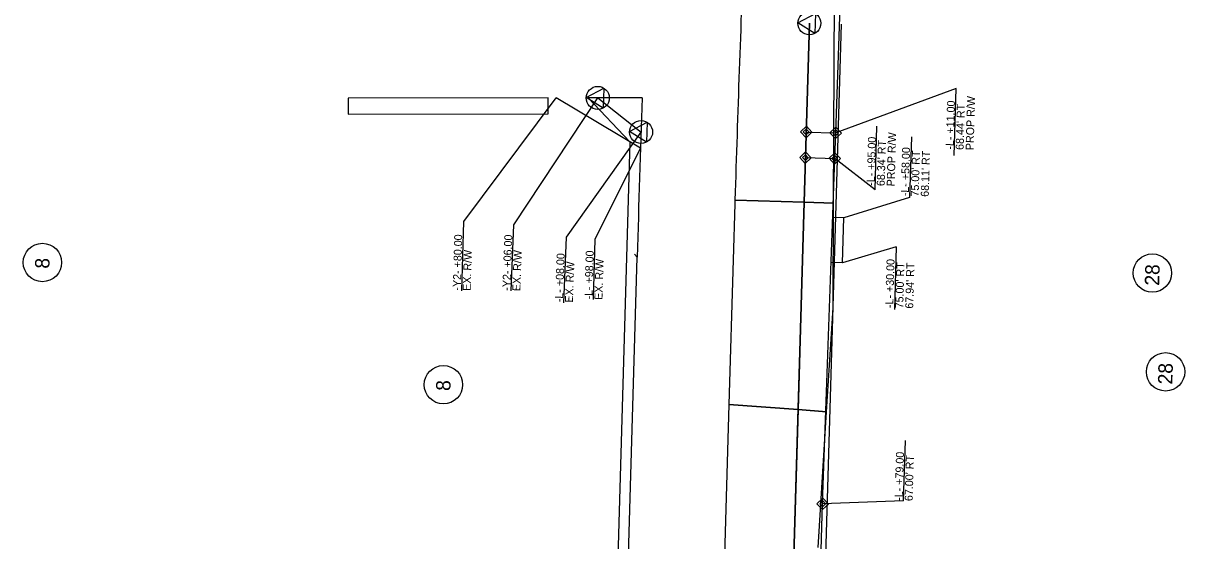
# Model space of a CAD drawing. Extents: x 2097272 to 2098144, y 685104 to 689282.
# Drawn here: x 2097282 to 2098008, y 686573 to 686896 of the extents above; entities that cross this region are included whole.
import ezdxf

# ---------------------------------------------------------------- set-up
doc = ezdxf.new("R2010")
doc.units = 0
for name, color, linetype in [('Prop Easement Aerial Utility', 7, 'Continuous'), ('Prop Easement Construction', 7, 'Continuous'), ('Prop Easement Construction Station Offsets', 7, 'Continuous'), ('Prop Easement Permanent Utility', 7, 'Continuous'), ('Prop Easement Permanent Utility Station Offsets', 7, 'Continuous'), ('Prop Parcel Number CELL', 7, 'Continuous'), ('Prop ROW Marker CELL', 7, 'Continuous'), ('Prop ROW Permanent Easement CELL', 7, 'Continuous'), ('Prop ROW RW Lines', 7, 'Continuous'), ('Prop ROW Station Offsets', 7, 'Continuous'), ('Scratch_Level_3', 7, 'Continuous'), ('Scratch_Level_5', 7, 'Continuous'), ('Scratch_Level_6', 7, 'Continuous')]:
    doc.layers.add(name, color=color, linetype=linetype)

msp = doc.modelspace()

# ---------------------------------------------------------------- linework, layer by layer
at = {"layer": 'Prop Easement Aerial Utility'}
for p, q in [((2097771.19, 686828.34), (2097789.62, 686827.81)), ((2097789.05, 686811.82), (2097789.62, 686827.81)), ((2097770.72, 686812.35), (2097789.05, 686811.82))]:
    msp.add_line(p, q, dxfattribs=at)
at = {"layer": 'Prop Easement Construction'}
for p, q in [((2097667.66, 686818.35), (2097614.97, 686849.63)), ((2097794.64, 686774.64), (2097787.75, 686774.84)), ((2097793.82, 686746.65), (2097794.64, 686774.64)), ((2097793.82, 686746.65), (2097786.76, 686746.86))]:
    msp.add_line(p, q, dxfattribs=at)
at = {"layer": 'Prop Easement Construction Station Offsets'}
for p, q in [((2097557.16, 686772.44), (2097614.97, 686849.63)), ((2097836.89, 686825.25), (2097835.79, 686787.41)), ((2097639.32, 686761.41), (2097667.66, 686818.35)), ((2097835.79, 686787.41), (2097794.64, 686774.64)), ((2097555.9, 686729.16), (2097557.16, 686772.44)), ((2097638.22, 686723.58), (2097639.32, 686761.41)), ((2097827.41, 686756.67), (2097793.82, 686746.65)), ((2097827.41, 686756.67), (2097826.27, 686717.32))]:
    msp.add_line(p, q, dxfattribs=at)
at = {"layer": 'Prop Easement Permanent Utility'}
for p, q in [((2097789.62, 686827.81), (2097812.51, 687476.77)), ((2097781.44, 686595.95), (2097789.05, 686811.82))]:
    msp.add_line(p, q, dxfattribs=at)
msp.add_lwpolyline([(2097776.41, 686423.02), (2097781.44, 686595.95)], dxfattribs=at)
at = {"layer": 'Prop Easement Permanent Utility Station Offsets'}
for p, q in [((2097864.87, 686855.45), (2097789.62, 686827.81)), ((2097863.66, 686813.61), (2097864.87, 686855.45)), ((2097814.27, 686792.2), (2097815.42, 686832.06)), ((2097814.27, 686792.2), (2097789.05, 686811.82)), ((2097832.07, 686597.77), (2097833.17, 686635.61)), ((2097832.07, 686597.77), (2097781.44, 686595.95))]:
    msp.add_line(p, q, dxfattribs=at)
at = {"layer": 'Prop Parcel Number CELL'}
for centre in [(2097293.93, 686746.8), (2097987.52, 686740.19), (2097995.75, 686678.46), (2097544.51, 686670.41)]:
    msp.add_circle(centre, 12, dxfattribs=at)
at = {"layer": 'Prop ROW Marker CELL'}
for p, q in [((2097640.97, 686849.64), (2097640.97, 686849.64)), ((2097667.99, 686828.34), (2097667.99, 686828.34)), ((2097771.19, 686828.34), (2097771.19, 686828.34)), ((2097789.62, 686827.81), (2097789.62, 686827.81)), ((2097770.72, 686812.35), (2097770.72, 686812.35)), ((2097789.05, 686811.82), (2097789.05, 686811.82)), ((2097781.44, 686595.95), (2097781.44, 686595.95))]:
    msp.add_line(p, q, dxfattribs=at)
for points in [[(2097776.52, 686889.95), (2097765.97, 686896.61), (2097777, 686902.44)], [(2097644.33, 686843.25), (2097633.77, 686849.91), (2097644.8, 686855.74)], [(2097671.35, 686821.96), (2097660.79, 686828.62), (2097671.83, 686834.45)]]:
    msp.add_lwpolyline(points, close=True, dxfattribs=at)
for centre in [(2097773.16, 686896.33), (2097640.97, 686849.64), (2097667.99, 686828.34)]:
    msp.add_circle(centre, 7.2, dxfattribs=at)
at = {"layer": 'Prop ROW Permanent Easement CELL'}
for points in [[(2097767.59, 686828.45), (2097771.29, 686831.94), (2097774.79, 686828.24), (2097771.08, 686824.75)], [(2097769.39, 686828.4), (2097771.24, 686830.14), (2097772.99, 686828.29), (2097771.14, 686826.54)], [(2097786.02, 686827.91), (2097789.72, 686831.41), (2097793.22, 686827.7), (2097789.51, 686824.21)], [(2097787.82, 686827.86), (2097789.67, 686829.61), (2097791.42, 686827.76), (2097789.57, 686826.01)], [(2097767.13, 686812.46), (2097770.83, 686815.95), (2097774.32, 686812.25), (2097770.62, 686808.75)], [(2097768.92, 686812.4), (2097770.78, 686814.15), (2097772.52, 686812.3), (2097770.67, 686810.55)], [(2097785.46, 686811.92), (2097789.16, 686815.42), (2097792.65, 686811.71), (2097788.95, 686808.22)], [(2097787.26, 686811.87), (2097789.11, 686813.62), (2097790.85, 686811.77), (2097789, 686810.02)], [(2097777.84, 686596.05), (2097781.54, 686599.55), (2097785.04, 686595.84), (2097781.34, 686592.35)], [(2097779.64, 686596), (2097781.49, 686597.75), (2097783.24, 686595.9), (2097781.39, 686594.15)]]:
    msp.add_lwpolyline(points, close=True, dxfattribs=at)
at = {"layer": 'Prop ROW RW Lines'}
for p, q in [((2097751.82, 686162.16), (2097773.16, 686896.33)), ((2097640.97, 686849.64), (2097667.99, 686828.34))]:
    msp.add_line(p, q, dxfattribs=at)
at = {"layer": 'Prop ROW Station Offsets'}
for p, q in [((2097588.47, 686770.42), (2097640.97, 686849.64)), ((2097621.33, 686762.59), (2097667.99, 686828.34)), ((2097586.89, 686729.01), (2097588.47, 686770.42)), ((2097619.76, 686721.64), (2097621.33, 686762.59))]:
    msp.add_line(p, q, dxfattribs=at)
at = {"layer": 'Scratch_Level_3'}
for p, q in [((2097769.91, 686784.41), (2097773.16, 686896.33)), ((2097726.82, 686785.78), (2097726.66, 686785.79)), ((2097726.66, 686785.79), (2097726.82, 686785.78)), ((2097769.91, 686784.41), (2097726.82, 686785.78)), ((2097726.82, 686785.78), (2097769.91, 686784.41)), ((2097766.15, 686654.89), (2097769.91, 686784.41)), ((2097725.55, 686748.46), (2097722.93, 686658.13)), ((2097722.93, 686658.13), (2097715.74, 686410.2)), ((2097766.15, 686654.89), (2097722.93, 686658.13)), ((2097722.93, 686658.13), (2097766.15, 686654.89)), ((2097759.19, 686415.67), (2097766.15, 686654.89))]:
    msp.add_line(p, q, dxfattribs=at)
for start, end in [(177.76589, 178.231975), (178.231975, 178.339124)]:
    msp.add_arc((2117687.16, 686169.66), 19970, start, end, dxfattribs=at)
at = {"layer": 'Scratch_Level_5'}
msp.add_line((2097770.38, 686112.18), (2097793.16, 686895.75), dxfattribs=at)
at = {"layer": 'Scratch_Level_6'}
for p, q in [((2097788.28, 686783.83), (2097788.84, 686918.42)), ((2097773.16, 686896.33), (2097769.91, 686784.41)), ((2097609.97, 686849.63), (2097484.97, 686849.59)), ((2097484.97, 686849.59), (2097484.97, 686839.59)), ((2097609.97, 686839.63), (2097609.97, 686849.63)), ((2097668.7, 686849.64), (2097634.97, 686849.63)), ((2097634.97, 686849.63), (2097660.96, 686822.23)), ((2097484.97, 686839.59), (2097609.97, 686839.63)), ((2097769.91, 686784.41), (2097766.15, 686654.89)), ((2097788.28, 686783.83), (2097769.91, 686784.41)), ((2097769.91, 686784.41), (2097788.28, 686783.83)), ((2097788, 686718.5), (2097788.28, 686783.83)), ((2097656.88, 686450.41), (2097665.57, 686750.2)), ((2097783.95, 686653.56), (2097788, 686718.5)), ((2097766.15, 686654.89), (2097759.19, 686415.67)), ((2097783.95, 686653.56), (2097766.15, 686654.89)), ((2097766.15, 686654.89), (2097783.95, 686653.56)), ((2097778.65, 686568.71), (2097783.95, 686653.56))]:
    msp.add_line(p, q, dxfattribs=at)
for points in [[(2097660.96, 686822.23), (2097650.89, 686475.77), (2097650.16, 686450.73)], [(2097665.57, 686750.2), (2097663.85, 686752.02), (2097665.57, 686750.2)]]:
    msp.add_lwpolyline(points, dxfattribs=at)
msp.add_arc((2117687.16, 686169.66), 20030, 178.054519, 178.339124, dxfattribs=at)

# ---------------------------------------------------------------- texts
at = {"layer": 'Prop Easement Construction Station Offsets'}
for s, p in [('-L- +58.00', (2097835.25, 686788.15)), ("75.00' RT", (2097841.5, 686787.97)), ("68.11' RT", (2097847.74, 686787.79)), ('-Y2- +80.00', (2097555.28, 686729.18)), ('EX. R/W', (2097561.52, 686729)), ('-L- +98.00', (2097637.59, 686723.59)), ('EX. R/W', (2097643.84, 686723.41)), ('-L- +30.00', (2097825.54, 686718.25)), ("75.00' RT", (2097831.79, 686718.07)), ("67.94' RT", (2097838.04, 686717.89))]:
    msp.add_text(s, height=5, rotation=88.33483, dxfattribs=at).set_placement(p)
at = {"layer": 'Prop Easement Permanent Utility Station Offsets'}
for s, p in [('PROP R/W', (2097875.78, 686816.93)), ('-L- +11.00', (2097863.29, 686817.29)), ("68.44' RT", (2097869.53, 686817.11)), ('PROP R/W', (2097826.45, 686794.31)), ('-L- +95.00', (2097813.96, 686794.67)), ("68.34' RT", (2097820.21, 686794.49)), ('-L- +79.00', (2097831.44, 686597.79)), ("67.00' RT", (2097837.69, 686597.61))]:
    msp.add_text(s, height=5, rotation=88.33483, dxfattribs=at).set_placement(p)
at = {"layer": 'Prop Parcel Number CELL'}
for s, p in [('8', (2097298.24, 686742.85)), ('28', (2097991.72, 686732.2)), ('28', (2097999.94, 686670.48)), ('8', (2097548.83, 686666.46))]:
    msp.add_text(s, height=9, rotation=88.33483, dxfattribs=at).set_placement(p)
at = {"layer": 'Prop ROW Station Offsets'}
for s, p in [('-Y2- +06.00', (2097586.26, 686729.04)), ('EX. R/W', (2097592.51, 686728.8)), ('-L- +08.00', (2097619.14, 686721.89)), ('EX. R/W', (2097625.39, 686721.65))]:
    msp.add_text(s, height=5, rotation=87.8037, dxfattribs=at).set_placement(p)

doc.saveas('drawing.dxf')
